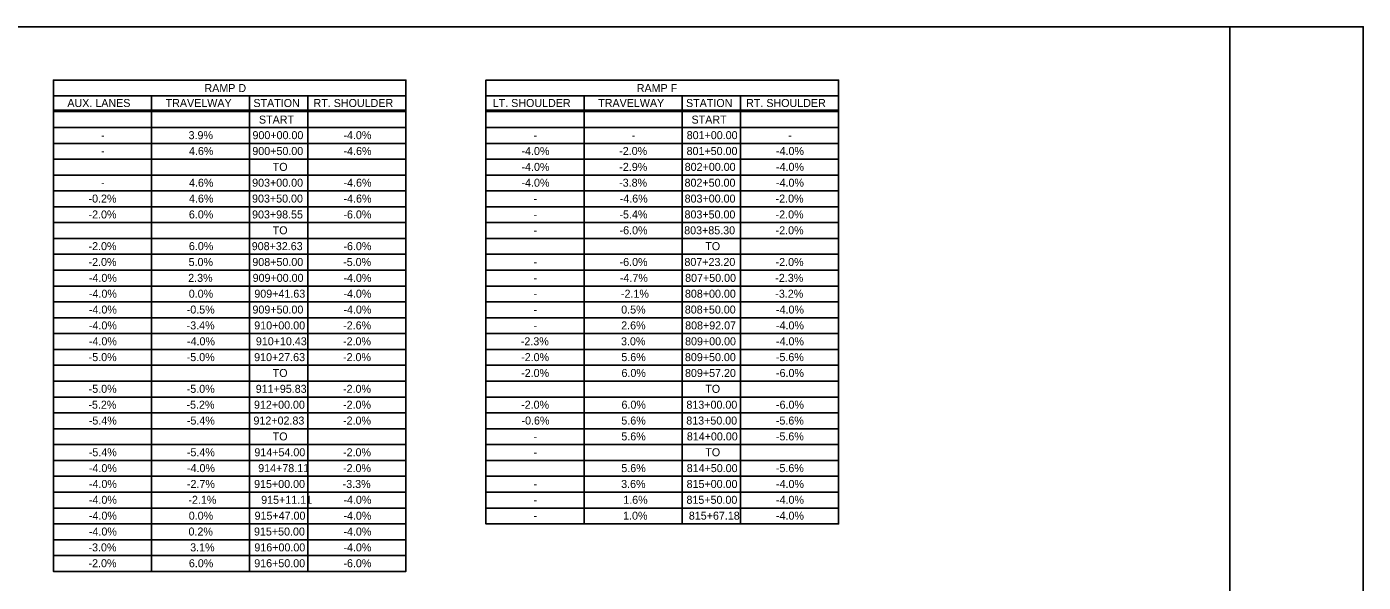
# Model space of a CAD drawing. Extents: x -15319374 to 1762012, y 465773 to 3693661.
# Drawn here: x -15314166 to -15313664, y 3691645 to 3691853 of the extents above; entities that cross this region are included whole.
import ezdxf

# ---------------------------------------------------------------- set-up
doc = ezdxf.new("R2010")
doc.units = 0
doc.layers.add('BORDER', color=7, linetype='Continuous')
doc.layers.add('DIMENSIONS', color=7, linetype='Continuous')

msp = doc.modelspace()

# ---------------------------------------------------------------- linework, layer by layer
at = {"layer": 'BORDER'}
for p, q in [((-15313714.43, 3691328.02), (-15313714.43, 3691853.02)), ((-15314155.52, 3691827.08), (-15314155.52, 3691708.88)), ((-15314118.75, 3691827.08), (-15314118.75, 3691648.87)), ((-15314081.98, 3691827.08), (-15314081.98, 3691648.87)), ((-15314060.11, 3691827.08), (-15314060.11, 3691648.87)), ((-15313993.34, 3691827.08), (-15313993.34, 3691708.88)), ((-15313956.57, 3691827.08), (-15313956.57, 3691666.69)), ((-15313919.81, 3691827.08), (-15313919.81, 3691666.69)), ((-15313897.93, 3691827.08), (-15313897.93, 3691666.69)), ((-15314155.52, 3691821.8), (-15314023.34, 3691821.8)), ((-15314155.52, 3691821.2), (-15314023.34, 3691821.2)), ((-15313993.34, 3691821.8), (-15313861.16, 3691821.8)), ((-15313993.34, 3691821.2), (-15313861.16, 3691821.2)), ((-15314155.52, 3691815.26), (-15314023.34, 3691815.26)), ((-15314155.52, 3691815.26), (-15314023.34, 3691815.26)), ((-15314155.52, 3691815.26), (-15314023.34, 3691815.26)), ((-15313993.34, 3691815.26), (-15313861.16, 3691815.26)), ((-15313993.34, 3691815.26), (-15313861.16, 3691815.26)), ((-15313993.34, 3691815.26), (-15313861.16, 3691815.26)), ((-15314155.52, 3691809.32), (-15314023.34, 3691809.32)), ((-15313993.34, 3691809.32), (-15313861.16, 3691809.32)), ((-15314155.52, 3691803.38), (-15314023.34, 3691803.38)), ((-15313993.34, 3691803.38), (-15313861.16, 3691803.38)), ((-15314155.52, 3691797.43), (-15314023.34, 3691797.43)), ((-15313993.34, 3691797.43), (-15313861.16, 3691797.43)), ((-15314155.52, 3691791.49), (-15314023.34, 3691791.49)), ((-15313993.34, 3691791.49), (-15313861.16, 3691791.49)), ((-15314155.52, 3691785.55), (-15314023.34, 3691785.55)), ((-15313993.34, 3691785.55), (-15313861.16, 3691785.55)), ((-15314155.52, 3691779.61), (-15314023.34, 3691779.61)), ((-15313993.34, 3691779.61), (-15313861.16, 3691779.61)), ((-15314155.52, 3691773.66), (-15314023.34, 3691773.66)), ((-15313993.34, 3691773.66), (-15313861.16, 3691773.66)), ((-15314155.52, 3691767.72), (-15314023.34, 3691767.72)), ((-15313993.34, 3691767.72), (-15313861.16, 3691767.72)), ((-15314155.52, 3691761.78), (-15314023.34, 3691761.78)), ((-15313993.34, 3691761.78), (-15313861.16, 3691761.78)), ((-15314155.52, 3691755.83), (-15314023.34, 3691755.83)), ((-15313993.34, 3691755.83), (-15313861.16, 3691755.83)), ((-15314155.52, 3691749.89), (-15314023.34, 3691749.89)), ((-15313993.34, 3691749.89), (-15313861.16, 3691749.89)), ((-15314155.52, 3691743.95), (-15314023.34, 3691743.95)), ((-15313993.34, 3691743.95), (-15313861.16, 3691743.95)), ((-15314155.52, 3691738.01), (-15314023.34, 3691738.01)), ((-15313993.34, 3691738.01), (-15313861.16, 3691738.01)), ((-15314155.52, 3691732.06), (-15314023.34, 3691732.06)), ((-15313993.34, 3691732.06), (-15313861.16, 3691732.06)), ((-15314155.52, 3691726.12), (-15314023.34, 3691726.12)), ((-15313993.34, 3691726.12), (-15313861.16, 3691726.12)), ((-15314155.52, 3691720.18), (-15314023.34, 3691720.18)), ((-15313993.34, 3691720.18), (-15313861.16, 3691720.18)), ((-15314155.52, 3691714.24), (-15314023.34, 3691714.24)), ((-15313993.34, 3691714.24), (-15313861.16, 3691714.24)), ((-15314155.52, 3691708.29), (-15314023.34, 3691708.29)), ((-15313993.34, 3691708.29), (-15313861.16, 3691708.29)), ((-15314155.52, 3691702.35), (-15314023.34, 3691702.35)), ((-15313993.34, 3691702.35), (-15313861.16, 3691702.35)), ((-15314155.52, 3691696.41), (-15314023.34, 3691696.41)), ((-15313993.34, 3691696.41), (-15313861.16, 3691696.41)), ((-15314155.52, 3691690.46), (-15314023.34, 3691690.46)), ((-15313993.34, 3691690.46), (-15313861.16, 3691690.46)), ((-15314155.52, 3691684.52), (-15314023.34, 3691684.52)), ((-15313993.34, 3691684.52), (-15313861.16, 3691684.52)), ((-15314155.52, 3691678.58), (-15314023.34, 3691678.58)), ((-15313993.34, 3691678.58), (-15313861.16, 3691678.58)), ((-15314155.52, 3691672.64), (-15314023.34, 3691672.64)), ((-15313993.34, 3691672.64), (-15313861.16, 3691672.64)), ((-15314155.52, 3691666.69), (-15314023.34, 3691666.69)), ((-15313993.34, 3691666.69), (-15313861.16, 3691666.69)), ((-15314155.52, 3691660.75), (-15314023.34, 3691660.75)), ((-15314155.52, 3691654.81), (-15314023.34, 3691654.81))]:
    msp.add_line(p, q, dxfattribs=at)
for points in [[(-15314464.43, 3691853.02), (-15313664.43, 3691853.02), (-15313664.43, 3691328.02), (-15314464.43, 3691328.02)], [(-15314155.52, 3691827.08), (-15314023.34, 3691827.08), (-15314023.34, 3691648.87), (-15314155.52, 3691648.87)], [(-15313993.34, 3691827.08), (-15313861.16, 3691827.08), (-15313861.16, 3691666.69), (-15313993.34, 3691666.69)]]:
    msp.add_lwpolyline(points, close=True, dxfattribs=at)
for points in [[(-15314155.52, 3691827.08), (-15314155.52, 3691833.02), (-15314023.34, 3691833.02), (-15314023.34, 3691827.08)], [(-15313993.34, 3691827.08), (-15313993.34, 3691833.02), (-15313861.16, 3691833.02), (-15313861.16, 3691827.08)]]:
    msp.add_lwpolyline(points, dxfattribs=at)

# ---------------------------------------------------------------- texts
at = {"layer": 'DIMENSIONS'}
for s, p in [('RAMP D', (-15314098.86, 3691828.55)), ('RAMP F', (-15313936.79, 3691828.55)), ('AUX. LANES', (-15314150.27, 3691822.94)), ('TRAVELWAY', (-15314113.43, 3691822.94)), ('STATION', (-15314080.52, 3691822.94)), ('RT. SHOULDER', (-15314057.98, 3691822.94)), ('LT. SHOULDER', (-15313990.79, 3691822.94)), ('TRAVELWAY', (-15313951.25, 3691822.94)), ('STATION', (-15313918.34, 3691822.94)), ('RT. SHOULDER', (-15313895.8, 3691822.94)), ('START', (-15314078.45, 3691816.72)), ('START', (-15313916.27, 3691816.72)), ('-', (-15314137.64, 3691810.89)), ('3.9%', (-15314104.83, 3691810.89)), ('900+00.00', (-15314080.87, 3691810.89)), ('-4.0%', (-15314046.78, 3691810.89)), ('-', (-15313975.47, 3691810.89)), ('-', (-15313938.7, 3691810.89)), ('801+00.00', (-15313918.08, 3691810.89)), ('-', (-15313880.05, 3691810.89)), ('-', (-15314137.64, 3691804.95)), ('4.6%', (-15314104.67, 3691804.95)), ('900+50.00', (-15314080.92, 3691804.95)), ('-4.6%', (-15314046.73, 3691804.95)), ('-4.0%', (-15313980.01, 3691804.95)), ('-2.0%', (-15313943.38, 3691804.95)), ('801+50.00', (-15313918.12, 3691804.95)), ('-4.0%', (-15313884.6, 3691804.95)), ('TO', (-15314073.29, 3691799)), ('-4.0%', (-15313980.01, 3691799)), ('-2.9%', (-15313943.34, 3691799)), ('802+00.00', (-15313918.83, 3691799)), ('-4.0%', (-15313884.6, 3691799)), ('4.6%', (-15314104.67, 3691793.06)), ('903+00.00', (-15314080.99, 3691793.06)), ('-4.6%', (-15314046.73, 3691793.06)), ('-4.0%', (-15313980.01, 3691793.06)), ('-3.8%', (-15313943.41, 3691793.06)), ('802+50.00', (-15313918.88, 3691793.06)), ('-4.0%', (-15313884.6, 3691793.06)), ('-0.2%', (-15314142.33, 3691787.12)), ('-', (-15314137.64, 3691793.06)), ('4.6%', (-15314104.67, 3691787.12)), ('903+50.00', (-15314081.03, 3691787.12)), ('-4.6%', (-15314046.73, 3691787.12)), ('-4.6%', (-15313943.19, 3691787.12)), ('803+00.00', (-15313918.86, 3691787.12)), ('-2.0%', (-15313884.74, 3691787.12)), ('-', (-15313975.47, 3691787.12)), ('-2.0%', (-15314142.33, 3691781.17)), ('6.0%', (-15314104.71, 3691781.17)), ('903+98.55', (-15314081.02, 3691781.17)), ('-6.0%', (-15314046.78, 3691781.17)), ('-', (-15313975.47, 3691781.17)), ('-5.4%', (-15313943.29, 3691781.17)), ('803+50.00', (-15313918.9, 3691781.17)), ('-2.0%', (-15313884.74, 3691781.17)), ('TO', (-15314073.29, 3691775.23)), ('-', (-15313975.47, 3691775.23)), ('-6.0%', (-15313943.24, 3691775.23)), ('803+85.30', (-15313919.02, 3691775.23)), ('-2.0%', (-15313884.74, 3691775.23)), ('-2.0%', (-15314142.33, 3691769.29)), ('6.0%', (-15314104.71, 3691769.29)), ('908+32.63', (-15314081.14, 3691769.29)), ('-6.0%', (-15314046.78, 3691769.29)), ('TO', (-15313911.11, 3691769.29)), ('-2.0%', (-15314142.33, 3691763.35)), ('5.0%', (-15314104.81, 3691763.35)), ('908+50.00', (-15314080.92, 3691763.35)), ('-5.0%', (-15314046.87, 3691763.35)), ('-', (-15313975.47, 3691763.35)), ('-6.0%', (-15313943.24, 3691763.35)), ('807+23.20', (-15313918.93, 3691763.35)), ('-2.0%', (-15313884.74, 3691763.35)), ('-4.0%', (-15314142.19, 3691757.4)), ('2.3%', (-15314104.97, 3691757.4)), ('909+00.00', (-15314080.82, 3691757.4)), ('-4.0%', (-15314046.78, 3691757.4)), ('-4.7%', (-15313943.12, 3691757.4)), ('807+50.00', (-15313918.67, 3691757.4)), ('-2.3%', (-15313884.86, 3691757.4)), ('-', (-15313975.47, 3691757.4)), ('-4.0%', (-15314142.19, 3691751.46)), ('0.0%', (-15314104.76, 3691751.46)), ('909+41.63', (-15314080.17, 3691751.46)), ('-4.0%', (-15314046.78, 3691751.46)), ('-', (-15313975.47, 3691751.46)), ('-2.1%', (-15313942.72, 3691751.46)), ('808+00.00', (-15313918.74, 3691751.46)), ('-3.2%', (-15313884.86, 3691751.46)), ('-4.0%', (-15314142.19, 3691745.52)), ('-0.5%', (-15314105.52, 3691745.52)), ('909+50.00', (-15314080.87, 3691745.52)), ('-4.0%', (-15314046.78, 3691745.52)), ('-', (-15313975.47, 3691745.52)), ('0.5%', (-15313942.63, 3691745.52)), ('808+50.00', (-15313918.79, 3691745.52)), ('-4.0%', (-15313884.6, 3691745.52)), ('-4.0%', (-15314142.19, 3691739.58)), ('-3.4%', (-15314105.54, 3691739.58)), ('910+00.00', (-15314080.21, 3691739.58)), ('-2.6%', (-15314046.87, 3691739.58)), ('-', (-15313975.47, 3691739.58)), ('2.6%', (-15313942.63, 3691739.58)), ('808+92.07', (-15313918.67, 3691739.58)), ('-4.0%', (-15313884.6, 3691739.58)), ('-4.0%', (-15314142.19, 3691733.63)), ('-4.0%', (-15314105.42, 3691733.63)), ('910+10.43', (-15314079.6, 3691733.63)), ('-2.0%', (-15314046.92, 3691733.63)), ('-2.3%', (-15313980.27, 3691733.63)), ('3.0%', (-15313942.7, 3691733.63)), ('809+00.00', (-15313918.69, 3691733.63)), ('-4.0%', (-15313884.6, 3691733.63)), ('-5.0%', (-15314142.28, 3691727.69)), ('-5.0%', (-15314105.52, 3691727.69)), ('910+27.63', (-15314080.24, 3691727.69)), ('-2.0%', (-15314046.92, 3691727.69)), ('-2.0%', (-15313980.15, 3691727.69)), ('5.6%', (-15313942.58, 3691727.69)), ('809+50.00', (-15313918.74, 3691727.69)), ('-5.6%', (-15313884.65, 3691727.69)), ('TO', (-15314073.29, 3691721.75)), ('-2.0%', (-15313980.15, 3691721.75)), ('6.0%', (-15313942.53, 3691721.75)), ('809+57.20', (-15313918.71, 3691721.75)), ('-6.0%', (-15313884.6, 3691721.75)), ('-5.0%', (-15314142.28, 3691715.81)), ('-5.0%', (-15314105.52, 3691715.81)), ('911+95.83', (-15314079.65, 3691715.81)), ('-2.0%', (-15314046.92, 3691715.81)), ('TO', (-15313911.11, 3691715.81)), ('-5.2%', (-15314142.38, 3691709.86)), ('-5.2%', (-15314105.61, 3691709.86)), ('912+00.00', (-15314080.3, 3691709.86)), ('-2.0%', (-15314046.92, 3691709.86)), ('-2.0%', (-15313980.15, 3691709.86)), ('6.0%', (-15313942.53, 3691709.86)), ('813+00.00', (-15313918.19, 3691709.86)), ('-6.0%', (-15313884.6, 3691709.86)), ('-5.4%', (-15314142.24, 3691703.92)), ('-5.4%', (-15314105.47, 3691703.92)), ('912+02.83', (-15314080.5, 3691703.92)), ('-2.0%', (-15314046.92, 3691703.92)), ('-0.6%', (-15313980.01, 3691703.92)), ('5.6%', (-15313942.58, 3691703.92)), ('813+50.00', (-15313918.24, 3691703.92)), ('-5.6%', (-15313884.65, 3691703.92)), ('TO', (-15314073.29, 3691697.98)), ('5.6%', (-15313942.58, 3691697.98)), ('814+00.00', (-15313918.03, 3691697.98)), ('-5.6%', (-15313884.65, 3691697.98)), ('-5.4%', (-15314142.24, 3691692.03)), ('-5.4%', (-15314105.47, 3691692.03)), ('914+54.00', (-15314080.16, 3691692.03)), ('-2.0%', (-15314046.92, 3691692.03)), ('-', (-15313975.47, 3691697.98)), ('TO', (-15313911.11, 3691692.03)), ('-', (-15313975.47, 3691692.03)), ('-4.0%', (-15314142.19, 3691686.09)), ('-4.0%', (-15314105.42, 3691686.09)), ('914+78.11', (-15314078.72, 3691686.09)), ('-2.0%', (-15314046.92, 3691686.09)), ('5.6%', (-15313942.58, 3691686.09)), ('814+50.00', (-15313918.08, 3691686.09)), ('-5.6%', (-15313884.65, 3691686.09)), ('-4.0%', (-15314142.19, 3691680.15)), ('-2.7%', (-15314105.44, 3691680.15)), ('915+00.00', (-15314080.26, 3691680.15)), ('-3.3%', (-15314047.06, 3691680.15)), ('-', (-15313975.47, 3691680.15)), ('3.6%', (-15313942.65, 3691680.15)), ('815+00.00', (-15313918.12, 3691680.15)), ('-4.0%', (-15313884.6, 3691680.15)), ('-4.0%', (-15314142.19, 3691674.21)), ('-2.1%', (-15314104.9, 3691674.21)), ('915+11.11', (-15314077.61, 3691674.21)), ('-4.0%', (-15314046.78, 3691674.21)), ('-', (-15313975.47, 3691674.21)), ('1.6%', (-15313941.87, 3691674.21)), ('815+50.00', (-15313918.17, 3691674.21)), ('-4.0%', (-15313884.6, 3691674.21)), ('-4.0%', (-15314142.19, 3691668.26)), ('0.0%', (-15314104.76, 3691668.26)), ('915+47.00', (-15314080.09, 3691668.26)), ('-4.0%', (-15314046.78, 3691668.26)), ('-', (-15313975.47, 3691668.26)), ('1.0%', (-15313941.92, 3691668.26)), ('815+67.18', (-15313917.28, 3691668.26)), ('-4.0%', (-15313884.6, 3691668.26)), ('-4.0%', (-15314142.19, 3691662.32)), ('0.2%', (-15314104.85, 3691662.32)), ('915+50.00', (-15314080.3, 3691662.32)), ('-4.0%', (-15314046.78, 3691662.32)), ('-3.0%', (-15314142.35, 3691656.38)), ('3.1%', (-15314104.22, 3691656.38)), ('916+00.00', (-15314080.16, 3691656.38)), ('-4.0%', (-15314046.78, 3691656.38)), ('-2.0%', (-15314142.33, 3691650.44)), ('6.0%', (-15314104.71, 3691650.44)), ('916+50.00', (-15314080.21, 3691650.44)), ('-6.0%', (-15314046.78, 3691650.44))]:
    msp.add_text(s, height=3, dxfattribs=at).set_placement(p)

doc.saveas('drawing.dxf')
